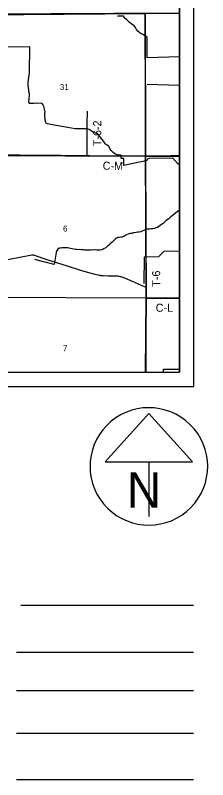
# Model space of a CAD drawing. Extents: x 0 to 34, y 0 to 22.
# Drawn here: x 7.74 to 9.1, y 11.22 to 16.62 of the extents above; entities that cross this region are included whole.
import ezdxf

# ---------------------------------------------------------------- set-up
doc = ezdxf.new("R2010")
doc.units = 0
for name, color, linetype in [('Default', 7, 'Continuous'), ('GM_X_County_Road', 7, 'Continuous'), ('GM_X_County_Road_Text', 7, 'Continuous'), ('GM_X_Minor_River', 7, 'Continuous'), ('GM_X_Section', 7, 'Continuous'), ('GM_X_Section_Text', 7, 'Continuous'), ('GM_X_Township_Road', 7, 'Continuous'), ('GM_X_Township_Road_Text', 7, 'Continuous'), ('SH_Cut_Line', 7, 'Continuous'), ('SH_Data', 7, 'Continuous')]:
    doc.layers.add(name, color=color, linetype=linetype)

msp = doc.modelspace()

# ---------------------------------------------------------------- linework, layer by layer
at = {"layer": 'Default'}
msp.add_lwpolyline([(7.5225, 14.1), (8.9, 14.1), (8.9, 16.6342), (8.7801, 16.6339), (8.659, 16.6337), (8.6215, 16.6337), (8.4971, 16.6335), (8.438, 16.6333), (8.3852, 16.6328), (8.295, 16.6324), (8.1582, 16.6322), (8.0835, 16.6316), (7.9964, 16.6311), (7.9032, 16.6305), (7.8317, 16.6301), (7.6731, 16.6285)], dxfattribs=at)
for points in [[(8.9, 15.6272), (8.9, 16.634), (8.6573, 16.6339), (8.6614, 15.6262)], [(8.9, 14.6228), (8.9, 15.6272), (8.6614, 15.6262), (8.6655, 14.6229)], [(7.5259, 14.1), (8.6609, 14.1), (8.6655, 14.6229), (7.529, 14.6277)], [(8.6609, 14.1), (8.9, 14.1), (8.9, 14.6228), (8.6655, 14.6229)]]:
    msp.add_lwpolyline(points, close=True, dxfattribs=at)
at = {"layer": 'GM_X_County_Road'}
for points in [[(7.5219, 15.6393), (7.5287, 15.6392), (7.5784, 15.6382), (7.6935, 15.6361), (7.7713, 15.6349), (7.8491, 15.6344), (7.9019, 15.6346), (7.9393, 15.6345), (7.9828, 15.6338), (8.0637, 15.633), (8.1228, 15.6321), (8.2161, 15.6312), (8.2458, 15.6312), (8.2489, 15.6311)], [(8.2489, 15.6311), (8.2505, 15.6311), (8.2688, 15.6305), (8.337, 15.6292), (8.4085, 15.6287), (8.4644, 15.6282), (8.5142, 15.6283), (8.6012, 15.6276), (8.6509, 15.628), (8.6601, 15.6282)], [(8.6601, 15.6282), (8.7006, 15.6291), (8.738, 15.6299), (8.8375, 15.631), (8.8748, 15.6311), (8.9, 15.6309)], [(7.5247, 14.8696), (7.7126, 14.9025), (7.8471, 14.927), (7.8589, 14.9287), (7.8638, 14.929), (7.8685, 14.9287), (7.8729, 14.9281), (7.8779, 14.927), (7.8896, 14.9232), (7.9513, 14.9019), (8.0162, 14.8804), (8.1011, 14.8539)], [(8.1011, 14.8539), (8.2031, 14.822), (8.2253, 14.8152)], [(8.2253, 14.8152), (8.2686, 14.8021), (8.3046, 14.7922), (8.3153, 14.7896), (8.3259, 14.7875), (8.3352, 14.7857), (8.3404, 14.7849), (8.3441, 14.7844), (8.3487, 14.7841), (8.353, 14.7838), (8.3631, 14.7833), (8.3973, 14.7824), (8.4501, 14.7813), (8.4581, 14.7809), (8.4655, 14.7801), (8.4727, 14.779), (8.4807, 14.7774), (8.4876, 14.7758), (8.4956, 14.7733), (8.5037, 14.7704), (8.513, 14.7668), (8.5674, 14.7437), (8.6524, 14.7069), (8.6632, 14.7032), (8.6659, 14.7022)], [(8.666, 14.6243), (8.6661, 14.6778), (8.6659, 14.7022)], [(8.6653, 14.1), (8.6657, 14.3887), (8.666, 14.6243)], [(8.666, 14.6243), (8.6759, 14.6245), (8.7101, 14.6252), (8.7536, 14.6257), (8.8376, 14.6261), (8.9, 14.6264)]]:
    msp.add_lwpolyline(points, dxfattribs=at)
at = {"layer": 'GM_X_Minor_River'}
msp.add_line((8.9, 16.125), (8.6728, 16.1321), dxfattribs=at)
for points in [[(8.9, 16.3276), (8.6722, 16.321), (8.6718, 16.4674), (8.6409, 16.4848), (8.6221, 16.4945), (8.6079, 16.5098), (8.5975, 16.5217), (8.5904, 16.5346), (8.5819, 16.5461), (8.5575, 16.5646), (8.5466, 16.5726), (8.5305, 16.5861), (8.5173, 16.5984), (8.5103, 16.6091), (8.5058, 16.6148), (8.466, 16.6152), (8.4634, 16.6187)], [(8.9, 15.5691), (8.89, 15.5699), (8.8534, 15.6128), (8.687, 15.6096), (8.6764, 15.6082), (8.6725, 15.5991), (8.6633, 15.5932), (8.5083, 15.561), (8.5082, 15.6096), (8.4892, 15.6094), (8.4892, 15.6333), (8.4668, 15.6335), (8.4483, 15.6409), (8.4419, 15.6448), (8.4322, 15.6521), (8.4176, 15.6655), (8.409, 15.6797), (8.4017, 15.6961), (8.39, 15.7041), (8.3814, 15.7088), (8.3776, 15.7138), (8.3721, 15.7233), (8.3225, 15.7856), (8.3085, 15.79), (8.2942, 15.7939), (8.278, 15.8043), (8.2626, 15.8147), (8.2445, 15.8191), (8.2232, 15.8197), (8.1645, 15.8199), (7.9917, 15.849), (7.9804, 15.8526), (7.969, 15.8538), (7.9596, 15.8592), (7.9563, 15.8684), (7.9505, 15.9113), (7.9514, 15.9295), (7.9535, 15.9408), (7.9495, 15.9515), (7.9481, 15.9633), (7.9463, 15.972), (7.9371, 15.9907), (7.9326, 15.9976), (7.9228, 16), (7.8951, 15.9991), (7.8857, 16.0004), (7.8731, 15.999), (7.8637, 15.9987), (7.85, 15.9988), (7.8458, 15.9985), (7.8425, 16.0016), (7.8391, 16.008), (7.8402, 16.0327), (7.842, 16.0562), (7.8429, 16.0676), (7.8389, 16.0801), (7.8376, 16.0961), (7.8338, 16.1268), (7.8345, 16.1496), (7.8425, 16.2151), (7.8449, 16.3991), (7.6819, 16.3958)], [(8.9, 15.2481), (8.893, 15.2407), (8.8831, 15.2332), (8.8719, 15.2227), (8.8593, 15.2126), (8.8478, 15.2047), (8.8375, 15.1961), (8.8252, 15.1849), (8.8134, 15.1766), (8.8038, 15.1688), (8.7942, 15.1601), (8.7846, 15.1519), (8.7747, 15.1448), (8.764, 15.1362), (8.7544, 15.1295), (8.7449, 15.1235), (8.7346, 15.1202), (8.7247, 15.1154), (8.7114, 15.1128), (8.7004, 15.1133), (8.6905, 15.1112), (8.6792, 15.1109), (8.6697, 15.1102), (8.6586, 15.1054), (8.6491, 15.1006), (8.6377, 15.0973), (8.627, 15.0921), (8.6171, 15.0899), (8.6069, 15.0889), (8.594, 15.0868), (8.5841, 15.0861), (8.5742, 15.0847), (8.5647, 15.0814), (8.5526, 15.0796), (8.5393, 15.0756), (8.5275, 15.0711), (8.5175, 15.0656), (8.5069, 15.0596), (8.4958, 15.0555), (8.486, 15.0553), (8.4757, 15.0531), (8.4662, 15.0509), (8.4559, 15.0469), (8.4444, 15.0375), (8.4345, 15.0296), (8.4249, 15.0195), (8.4122, 15.0079), (8.4026, 14.9981), (8.3915, 14.9887), (8.3812, 14.9794), (8.3705, 14.9745), (8.3602, 14.9671), (8.3507, 14.9649), (8.3404, 14.9631), (8.3306, 14.9624), (8.3173, 14.9637), (8.3063, 14.9642), (8.2965, 14.9632), (8.2866, 14.964), (8.2753, 14.9634), (8.2654, 14.9616), (8.2533, 14.9636), (8.2419, 14.9634), (8.2317, 14.9635), (8.2215, 14.9647), (8.2097, 14.9656), (8.1972, 14.9661), (8.187, 14.9658), (8.1764, 14.9675), (8.1666, 14.9676), (8.1545, 14.9696), (8.1435, 14.9708), (8.1325, 14.9748), (8.1227, 14.9771), (8.1121, 14.9791), (8.1023, 14.9792), (8.0921, 14.9801), (8.0826, 14.9787), (8.0723, 14.978)], [(8.0342, 14.9599), (8.0163, 14.861), (7.8796, 14.8974)], [(8.0723, 14.978), (8.0625, 14.9774), (8.0522, 14.976), (8.0419, 14.9689), (8.0357, 14.9587), (8.0318, 14.9489), (8.031, 14.9455)], [(8.9, 14.9536), (8.7935, 14.9557), (8.7532, 14.9148), (8.6505, 14.9128), (8.6496, 14.7262)], [(8.7878, 14.1), (8.788, 14.122), (8.9, 14.1215)]]:
    msp.add_lwpolyline(points, dxfattribs=at)
at = {"layer": 'GM_X_Section'}
for points in [[(7.5172, 16.6244), (8.6573, 16.6339), (8.6614, 15.6262), (7.5223, 15.6321), (7.5171, 16.6191)], [(7.5223, 15.6321), (8.6614, 15.6262), (8.6655, 14.6229), (7.529, 14.6277)]]:
    msp.add_lwpolyline(points, close=True, dxfattribs=at)
at = {"layer": 'GM_X_Township_Road'}
for points in [[(8.6601, 15.6282), (8.66, 15.6352), (8.6601, 15.7906), (8.6601, 15.943), (8.6597, 16.2165), (8.6595, 16.3999), (8.6592, 16.6332)], [(8.2489, 15.6311), (8.249, 15.6323), (8.249, 15.6375), (8.2492, 15.6623), (8.2501, 15.7212), (8.2501, 15.7956), (8.2499, 15.8482), (8.2503, 15.8823), (8.2512, 15.9164), (8.2517, 15.9319), (8.2518, 15.9438)], [(8.6659, 14.7022), (8.6649, 14.8487), (8.6639, 14.9855), (8.6635, 15.0725), (8.663, 15.1316), (8.662, 15.3399), (8.661, 15.4891), (8.6601, 15.6282)]]:
    msp.add_lwpolyline(points, dxfattribs=at)
at = {"layer": 'SH_Cut_Line'}
msp.add_lwpolyline([(2.1, 20.6957), (2.1, 14.1), (8.9, 14.1), (8.9, 20.8277), (8.6079, 20.8216), (7.476, 20.811), (6.4789, 20.8005), (5.4741, 20.7803), (4.4698, 20.7584), (3.7151, 20.7343), (2.4566, 20.7022)], close=True, dxfattribs=at)
at = {"layer": 'SH_Data'}
for p, q in [((9, 21), (9, 14)), ((8.9, 20.9), (8.9, 14.1)), ((2.1, 14.1), (8.9, 14.1)), ((2, 14), (9, 14)), ((8.6845, 13.8091), (8.3769, 13.4678)), ((8.9921, 13.4678), (8.6845, 13.8091)), ((8.3769, 13.4678), (8.9921, 13.4678)), ((8.6845, 13.4678), (8.6845, 13.0811)), ((8.6845, 13.4353), (8.6845, 13.4353)), ((8.6845, 13.4353), (8.6845, 13.4353)), ((7.7827, 12.4553), (9, 12.4553)), ((9, 12.1207), (7.75, 12.1207)), ((9, 11.8491), (7.75, 11.8491)), ((9, 11.5491), (7.75, 11.5491)), ((9, 11.2223), (7.75, 11.2223))]:
    msp.add_line(p, q, dxfattribs=at)
msp.add_arc((8.6845, 13.4353), 0.4148, 129.7798, 129.7633, dxfattribs=at)

# ---------------------------------------------------------------- texts
at = {"layer": 'GM_X_County_Road_Text'}
for s, rotation, p in [('C-M', 359.2678, (8.3585, 15.5309)), ('C-L', 0, (8.7325, 14.5275))]:
    msp.add_text(s, height=0.05682, rotation=rotation, dxfattribs=at).set_placement(p)
at = {"layer": 'GM_X_Section_Text'}
for s, height, p in [('31', 0.04186, (8.0571, 16.0946)), ('6', 0.0419, (8.0792, 15.0938)), ('7', 0.0419, (8.0788, 14.2485))]:
    msp.add_text(s, height=height, rotation=0, dxfattribs=at).set_placement(p)
at = {"layer": 'GM_X_Township_Road_Text'}
for s, rotation, p in [('T-6-2', 90, (8.3486, 15.6971)), ('T-6', 90.4772, (8.7653, 14.7046))]:
    msp.add_text(s, height=0.05682, rotation=rotation, dxfattribs=at).set_placement(p)
at = {"layer": 'SH_Data'}
msp.add_text('N', height=0.25, dxfattribs=at).set_placement((8.5292, 13.144))

doc.saveas('drawing.dxf')
